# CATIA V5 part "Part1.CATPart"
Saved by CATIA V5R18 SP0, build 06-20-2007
Part number: Part1
Bounding box of the stored display mesh (mm): x -100 to 100, y -50 to 50, z -20 to 20
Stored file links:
  D:\Shriniwas\v5_r19\c16_CAT_v5r19\c16_Part\Presmatic Joint\Part1.CATPart
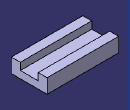
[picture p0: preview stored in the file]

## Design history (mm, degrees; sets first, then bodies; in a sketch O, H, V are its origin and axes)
Body1 (main body)
  Sketch1 on yz-plane, origin (0, 0, 0), H (0, 1, 0), V (0, 0, 1)
    line L1 (50, 20) -> (50, -20)
    line L2 (50, -20) -> (-50, -20)
    line L3 (-50, -20) -> (-50, 20)
    point P1 (50, 20)
    point P4 (-50, 20)
    point P5 (0, 8.2157)
    line L4 (25, 20) -> (25, 0)
    line L5 (25, 0) -> (-25, 0)
    line L6 (-25, 0) -> (-25, 20)
    line L7 (-25, 20) -> (-50, 20)
    point P10 (-50, 20)
    line L8 (25, 20) -> (50, 20)
    point P11 (50, 20)
    distance V L3 = 50
    distance L6 V = 25
    length L5 = 50
    distance L2 L5 = 20
    length L3 = 40
    vertical: L1 V, L3 V, L4 V, L6 V
    horizontal: L2 H, L5 H, L7 H, L8 H
    equidistance: L1 L3 O, L4 L6 P5
    coincidence: P4 P10, P11 L1, P11 P1, L7 L8, H L5
  Pad1: profile Sketch1, direction (1, 0, 0), length 100, mirrored extent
